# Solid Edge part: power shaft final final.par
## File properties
Author: vinurabandara
Template: iso metric part.par
Last saved by: Nimesh.N
Revision: 69
Application: Solid Edge
Density: 7800.000 kg/m^3
Accuracy: 0.990
Username: Nimesh.N
Material: Steel - Free Cutting:1.0764 , 36SMn14
Face Style: Steel
Fill Style: ANSI32(Steel)
Grouping: Steel\Steel - Free Cutting ( Higher P or S content)
LibraryName: Materials-DIN
Coef. of Thermal Exp: 1.1e-05
Thermal Conductivity: 14.0
Specific Heat: 440.0
Modulus of Elasticity: 210000003072.0
Poisson's Ratio: 0.28
Yield Stress: 420000000.0
Ultimate Stress: 670000000.0
Elongation: 0.0
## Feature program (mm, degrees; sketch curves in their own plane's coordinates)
sketch for "unnamed Protrusion 1" plane through (0, 0, 0) normal (0, -1, 0) x-axis (1, 0, 0)
  circle centre (0, 0) radius 40.625
extrude "unnamed Protrusion 1" add finite 1020 along -normal
sketch for "unnamed Cutout 1" plane through (0, 0, 0) normal (0, -1, 0) x-axis (1, 0, 0)
  line (7.7259, 39.8836) -> (4.5358, 32.1819)
  arc centre (0, 0) radius 32.5 from (-4.5358, 32.1819) to (4.5358, 32.1819) cw
  line (-4.5358, 32.1819) -> (-7.7259, 39.8836)
  arc centre (0, 0) radius 40.625 from (-7.7259, 39.8836) to (7.7259, 39.8836) cw
extrude "unnamed Cutout 1" cut through along -normal
pattern "unnamed Pattern 1" of "unnamed Cutout 1"
pattern "unnamed Pattern 2"
sketch for "unnamed Protrusion 2" plane through (0, 0, 0) normal (0, -1, 0) x-axis (0.382683, 0, 0.92388)
  circle centre (0, 0) radius 40.625
extrude "unnamed Protrusion 2" add finite 5 along +normal
sketch for "ExtrudedProtrusion_3" plane through (0, -5, 0) normal (0, -1, 0) x-axis (1, 0, 0)
  circle centre (0, 0) radius 32.5
extrude "ExtrudedProtrusion_3" add finite 85 along +normal
sketch for "BearingGuideStep" plane through (0, -5, 0) normal (0, -1, 0) x-axis (1, 0, 0)
extrude "BearingGuideStep" add finite 46.5 along +normal
sketch for "unnamed Protrusion 3" plane through (0, 1020, 0) normal (0, 1, 0) x-axis (0.382683, 0, 0.92388)
  circle centre (0, 0) radius 32.5
extrude "unnamed Protrusion 3" add finite 120 along +normal
sketch for "ExtrudedProtrusion_5" plane through (0, 1140, 0) normal (0, 1, 0) x-axis (1, 0, 0)
  circle centre (0, 0) radius 27.5
extrude "ExtrudedProtrusion_5" add finite 180 along +normal
sketch for "unnamed Cutout 2" plane through (0, 0, -22) normal (0, 0, 1) x-axis (1, 0, 0)
  line (4, 1145) -> (-4, 1145)
  arc centre (-4, 1150) radius 5 from (-4, 1145) to (-9, 1150) cw
  line (-9, 1150) -> (-9, 1194)
  arc centre (-4, 1194) radius 5 from (-4, 1199) to (-9, 1194) ccw
  line (-4, 1199) -> (4, 1199)
  arc centre (4, 1194) radius 5 from (9, 1194) to (4, 1199) ccw
  line (9, 1194) -> (9, 1150)
  arc centre (4, 1150) radius 5 from (9, 1150) to (4, 1145) cw
  dimension (linear) = 9
  dimension (linear) = 4
extrude "unnamed Cutout 2" cut through along -normal
sketch for "ExtrudedCutout_4" #1 plane through (0, 1290, 0) normal (0, -1, 0) x-axis (1, 0, 0)
  circle centre (0, 0) radius 27.5
sketch for "ExtrudedCutout_4" #2 plane through (0, 1290, 0) normal (0, -1, 0) x-axis (1, 0, 0)
  circle centre (0, 0) radius 26
extrude "ExtrudedCutout_4" cut finite 2.15 along -normal
chamfer "Chamfer_1" setback 3
chamfer "Chamfer_2" setback 3
sketch for "unnamed RevolvedCutout 1" plane through (0, 0, 0) normal (1, 0, 0) x-axis (0, 1, 0)
revolve "unnamed RevolvedCutout 1" cut full turn 360 deg
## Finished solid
Body 1: solid body, 59 faces, 136 edges, 80 vertices.
  Faces by surface: plane 45, cylinder 12, cone 2
  Edges by curve: line 78, circle 54, intersection 4
Bounding box of the edges (mm): 81.250 x 1410.000 x 81.250, from (-40.625, -90, -40.625) to (40.625, 1320, 40.625).
Cylindrical faces by radius (mm): R5 x4, R26 x1, R27.5 x2, R31 x1, R32.5 x3, R40.625 x1
Conical faces (half-angle, radius in mm at the cone's reference point): 45 deg R27.5 x1, 45 deg R32.5 x1
Planar faces by outward normal: +x 1, +y 21, -x 1, -y 5, -z 1, oblique 16
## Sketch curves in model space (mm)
line (0, 1066, 32.5) -> (0, 1066, 31)
line (0, 1066, 31) -> (0, 1063.35, 31)
line (0, 1063.35, 31) -> (0, 1063.35, 32.5)
line (0, 1063.35, 32.5) -> (0, 1066, 32.5)
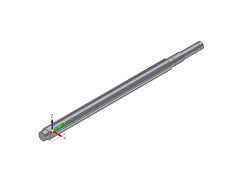
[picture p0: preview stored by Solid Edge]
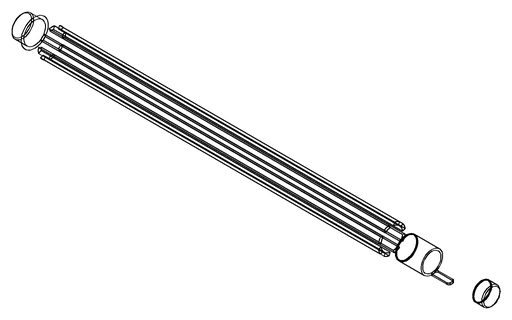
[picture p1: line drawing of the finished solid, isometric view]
